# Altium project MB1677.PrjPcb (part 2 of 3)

## Sheet JTAG.SchDoc: JTAG and TRACE
size A4; Date: Not used; ApprovedBy: Not used; CheckedBy: Not used; Author: Not used; CompanyName: STMicroelectronics; DrawnBy: Not used; Engineer: Not used; Organization: Not used; Address1: Not used; Address2: Not used; Address3: Not used; Address4: Not used; DocumentNumber: 14; Revision: Not used; SheetNumber: 14; SheetTotal: 15
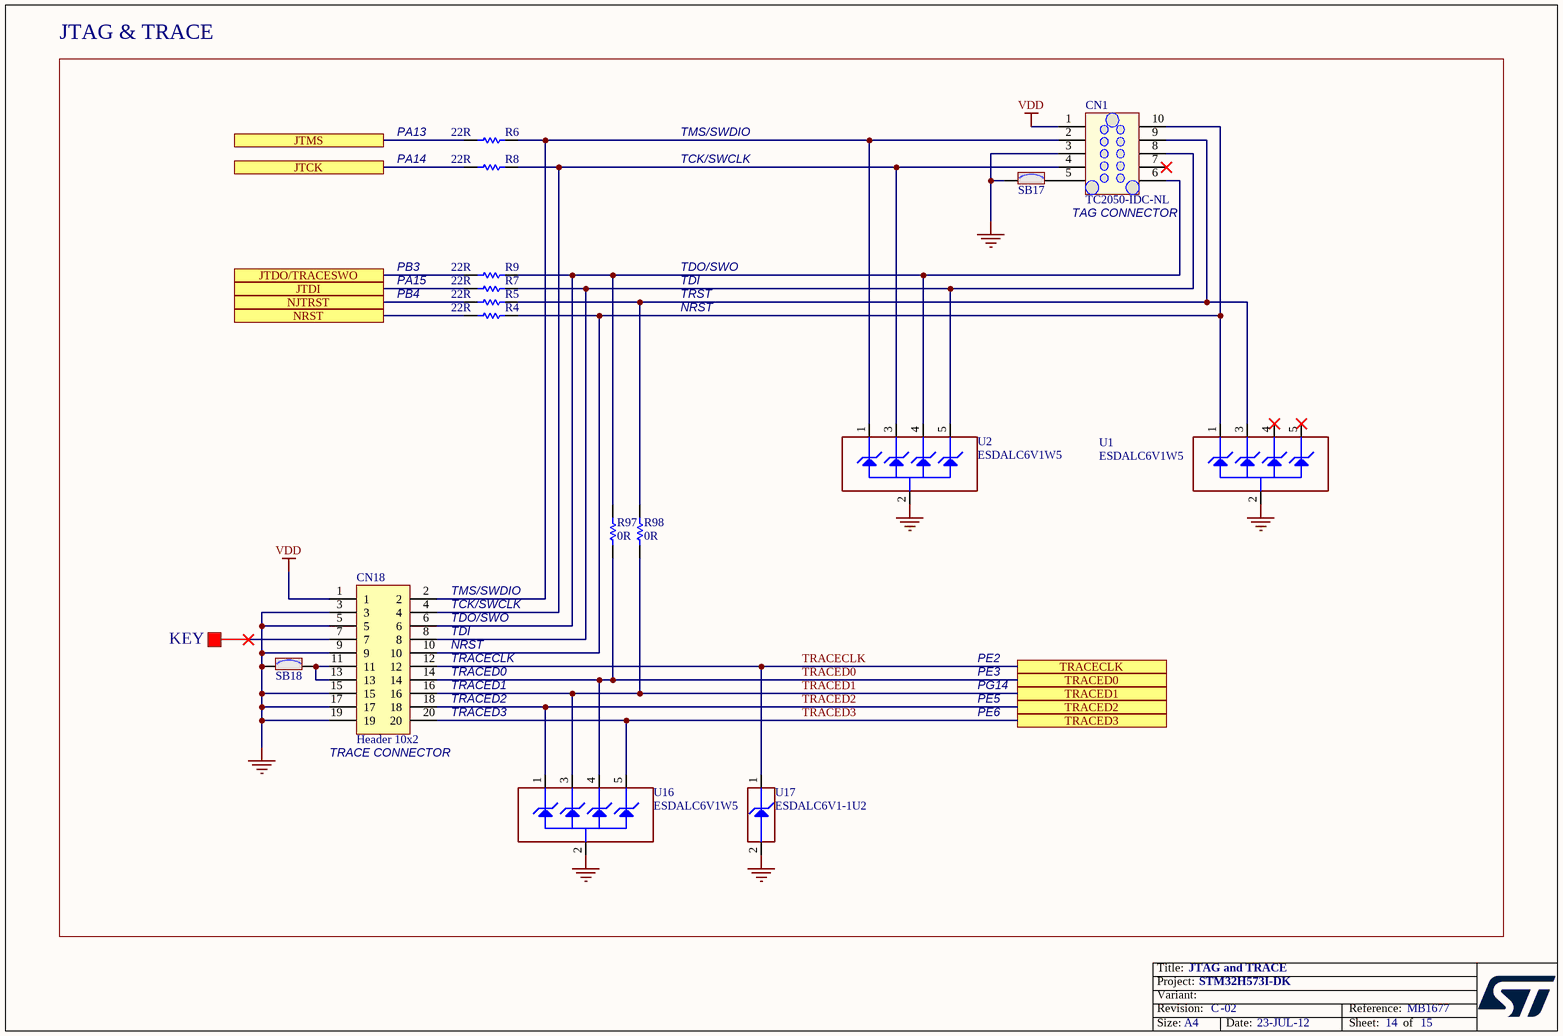
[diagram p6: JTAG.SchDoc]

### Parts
CN1  value TC2050-IDC-NL  [CON_TAG-C_TC2050-IDC-NL]  (hidden comment: Tag-10-C)
CN18  Header 10x2  [CON_SAMTEC_FTSH-110-01-L-DV]
R4  value 22R  [R0603]  (hidden comment: Resistor)
R5  value 22R  [R0603]  (hidden comment: Resistor)
R6  value 22R  [R0603]  (hidden comment: Resistor)
R7  value 22R  [R0603]  (hidden comment: Resistor)
R8  value 22R  [R0603]  (hidden comment: Resistor)
R9  value 22R  [R0603]  (hidden comment: Resistor)
R97  value 0R  [R0402]  (hidden comment: Resistor)
R98  value 0R  [R0402]  (hidden comment: Resistor)
SB17  SB_ON  [SOLDER-BRIDGE_R0603-0R]  (value not drawn)
SB18  SB_ON  [SOLDER-BRIDGE_R0603-0R]  (value not drawn)
U1  ESDALC6V1W5  [ESD_SOT323-5L]
U2  ESDALC6V1W5  [ESD_SOT323-5L]
U16  ESDALC6V1W5  [ESD_SOT323-5L]
U17  value ESDALC6V1-1U2  [ESD_ST0201]  (hidden comment: ESD-TRANSIL)

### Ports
JTCK, JTDI, JTDO/TRACESWO, JTMS, NJTRST, NRST, TRACECLK, TRACED0, TRACED1, TRACED2, TRACED3

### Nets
GND: CN1.3 CN18.3 CN18.5 CN18.9 CN18.15 CN18.17 CN18.19 SB17.1 SB18.1 U1.2(GND) U2.2(GND) U16.2(GND) U17.2(GND)
VDD: CN1.1 CN18.1
JTCK: R8.2 ; port JTCK
JTDI: R7.2 ; port JTDI
JTDO: R9.2 ; port JTDO/TRACESWO
JTMS: R6.2 ; port JTMS
NJTRST: R5.2 ; port NJTRST
NRST: R4.2 ; port NRST
TRACECLK: CN18.12 U17.1(IO1) ; port TRACECLK
TRACED0: CN18.14 R97.1 U16.4(IO3) ; port TRACED0
TRACED1: CN18.16 R98.1 U16.3(IO2) ; port TRACED1
TRACED2: CN18.18 U16.1(IO1) ; port TRACED2
TRACED3: CN18.20 U16.5(IO4) ; port TRACED3
NetCN1_2: CN1.2 CN18.2 R6.1 U2.1(IO1)
NetCN1_4: CN1.4 CN18.4 R8.1 U2.3(IO2)
NetCN1_5: CN1.5 SB17.2
NetCN1_6: CN1.6 CN18.6 R9.1 R97.2 U2.4(IO3)
NetCN1_8: CN1.8 CN18.8 R7.1 U2.5(IO4)
NetCN1_9: CN1.9 R5.1 R98.2 U1.3(IO2)
NetCN1_10: CN1.10 CN18.10 R4.1 U1.1(IO1)
NetCN18_11: CN18.11 CN18.13 SB18.2

Not connected (* = marked no-connect by the designer): CN1 7*; CN18 7*; U1 4(IO3)* 5(IO4)*

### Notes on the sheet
- JTAG & TRACE
- PA13
- PA14
- TMS/SWDIO
- TCK/SWCLK
- TAG CONNECTOR
- PB3
- PA15
- PB4
- TDO/SWO
- TDI
- TRST
- NRST
- KEY
- (near CN18) TMS/SWDIO
- (near CN18) TCK/SWCLK
- (near CN18) TDO/SWO
- (near CN18) TDI
- (near CN18) NRST
- (near CN18) TRACECLK
- (near CN18) TRACED0
- (near CN18) TRACED1
- (near CN18) TRACED2
- (near CN18) TRACED3
- PE2
- PE3
- PG14
- PE5
- PE6
- (near CN18) TRACE CONNECTOR

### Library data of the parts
CN1 = MCD-00031: Tag_Connector Header, 10x2, No legs; Manufacturer_Part_Number: TC2050-IDC-NL-FP; Manufacturer: TAG-CONNECT LLC; Provided_By: SUBCO
CN18 = MCD-00557: Header, 10x2, 1.27mm, VR, SMD, T=3.05mm; BMS_Part_Number: 9183690; Part_Type: Connector; Part_Preference: Recommended; Manufacturer: SAMTEC; Manufacturer_Part_Number: FTSH-110-01-L-DV; Order_Code_RS: 767-6774; Component_Country_Of_Origin: China, Costa Rica, Malaysia, United States, Vietnam; ShowFields: YES; ID: 3188
R4-R9 = MCD-00066: Resistor,22R,0603,1%,1/10W; Manufacturer_Part_Number: RC0603FR-0722RL; Manufacturer: YAGEO; Provided_By: SUBCO
R97 R98 = MCD-00052: Resistor, 0R, 0402, +/-5%, 1/16W; Part_Preference: Recommended; Manufacturer: YAGEO; Manufacturer_Part_Number: RC0402JR-070RL; Order_Code_RS: 618-5804; Component_Country_Of_Origin: China
SB17 SB18 = MCD-00071: Solder Bridge ON; Part_Type: Mechanical; Manufacturer_Part_Number: RC0603JR-070RL; Manufacturer: YAGEO; Provided_By: SUBCO
U1 U2 U16 = MCD-00136: Dual Transil array for ESD protection; Part_Type: Diode; Manufacturer: STMICROELECTRONICS; BMS_Part_Number: 9151112; Provided_By: SUBCO with ST control
U17 = MCD-00170: ESD protection 6V1; BMS_Part_Number: 9151132; Part_Type: Diode; Part_Preference: Recommended; Manufacturer: STMICROELECTRONICS; Manufacturer_HQ_COO: EU; Component_Country_Of_Origin: China; ShowFields: YES; ID: 2696

## Sheet Ethernet.SchDoc: Ethernet
size A4; Date: Not used; ApprovedBy: Not used; CheckedBy: Not used; Author: Not used; CompanyName: STMicroelectronics; DrawnBy: Not used; Engineer: Not used; Organization: Not used; Address1: Not used; Address2: Not used; Address3: Not used; Address4: Not used; DocumentNumber: 9; Revision: Not used; SheetNumber: 9; SheetTotal: 15
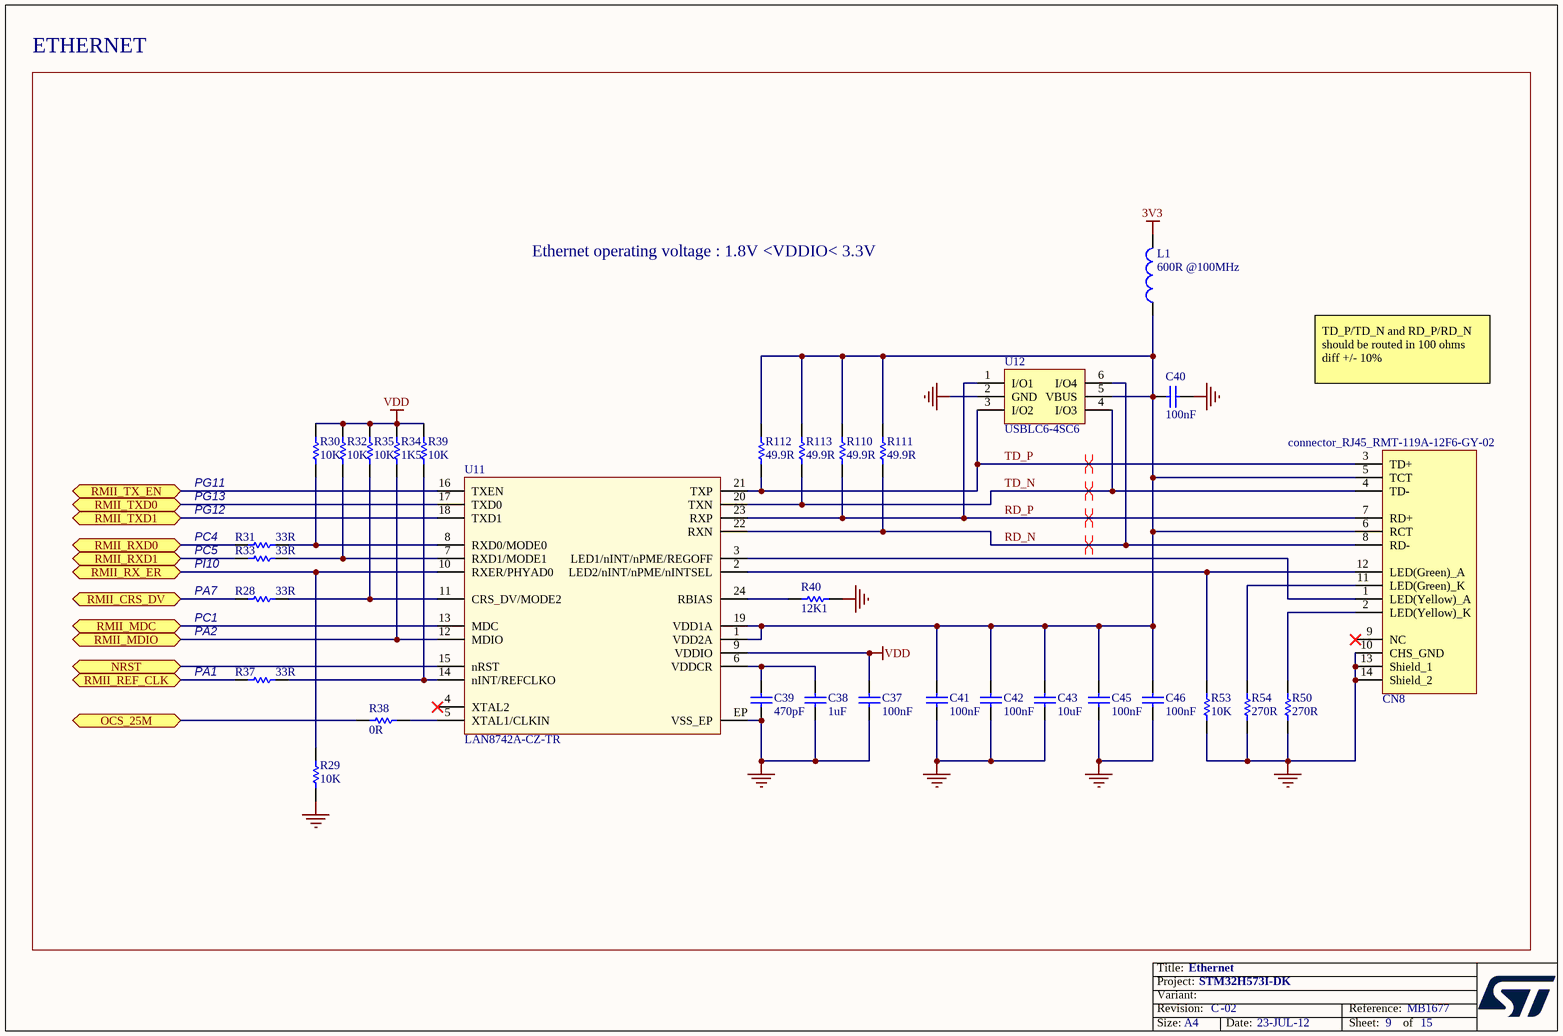
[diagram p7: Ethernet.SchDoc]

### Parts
C37  value 100nF  [C0603]  (hidden comment: Capacitor)
C38  value 1uF  [C0402]  (hidden comment: Capacitor)
C39  value 470pF  [C0402]  (hidden comment: Capacitor)
C40  value 100nF  [C0603]  (hidden comment: Capacitor)
C41  value 100nF  [C0603]  (hidden comment: Capacitor)
C42  value 100nF  [C0603]  (hidden comment: Capacitor)
C43  value 10uF  [C0603]  (hidden comment: Capacitor)
C45  value 100nF  [C0603]  (hidden comment: Capacitor)
C46  value 100nF  [C0603]  (hidden comment: Capacitor)
CN8  value connector_RJ45_RMT-119A-12F6-GY-02  [CON_RJ45_PHC_RMT-119A-12F6-GY-02]  (hidden comment: RJ45_RTS-119A-12F6-GY-02)
L1  value 600R @100MHz  [L0603]  (hidden comment: BEAD)
R28  value 33R  [R0402]  (hidden comment: Resistor)
R29  value 10K  [R0402]  (hidden comment: Resistor)
R30  value 10K  [R0402]  (hidden comment: Resistor)
R31  value 33R  [R0402]  (hidden comment: Resistor)
R32  value 10K  [R0402]  (hidden comment: Resistor)
R33  value 33R  [R0402]  (hidden comment: Resistor)
R34  value 1K5  [R0402]  (hidden comment: Resistor)
R35  value 10K  [R0402]  (hidden comment: Resistor)
R37  value 33R  [R0402]  (hidden comment: Resistor)
R38  value 0R  [R0402]  (hidden comment: Resistor)
R39  value 10K  [R0402]  (hidden comment: Resistor)
R40  value 12K1  [R0402]  (hidden comment: Resistor)
R50  value 270R  [R0402]  (hidden comment: Resistor)
R53  value 10K  [R0402]  (hidden comment: Resistor)
R54  value 270R  [R0402]  (hidden comment: Resistor)
R110  value 49.9R  [R0402]  (hidden comment: Resistor)
R111  value 49.9R  [R0402]  (hidden comment: Resistor)
R112  value 49.9R  [R0402]  (hidden comment: Resistor)
R113  value 49.9R  [R0402]  (hidden comment: Resistor)
U11  LAN8742A-CZ-TR  [ICC_VQFN24-EPAD_4X4_P050]
U12  USBLC6-4SC6  [ESD_SOT23-6L]

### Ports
NRST (bidir), OCS_25M (bidir), RMII_CRS_DV (bidir), RMII_MDC (bidir), RMII_MDIO (bidir), RMII_REF_CLK (bidir), RMII_RX_ER (bidir), RMII_RXD0 (bidir), RMII_RXD1 (bidir), RMII_TX_EN (bidir), RMII_TXD0 (bidir), RMII_TXD1 (bidir)

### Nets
3V3: L1.2
GND: C37.1 C38.1 C39.1 C40.2 C41.1 C42.1 C43.1 C45.1 C46.1 CN8.10(CHS_GND) CN8.13(Shield_1) CN8.14(Shield_2) R29.2 R40.2 R50.1 R53.1 R54.1 U11.EP(VSS_EP) U12.2(GND)
VDD: C37.2 R30.2 R32.2 R34.2 R35.2 R39.2 U11.9(VDDIO)
NRST: U11.15(nRST) ; port NRST
OCS_25M: R38.2 ; port OCS_25M
RD_N: CN8.8(RD-) R111.1 U11.22(RXN) U12.6(I/O4)
RD_P: CN8.7(RD+) R110.1 U11.23(RXP) U12.1(I/O1)
RMII_CRS_DV: R28.1 ; port RMII_CRS_DV
RMII_MDC: U11.13(MDC) ; port RMII_MDC
RMII_MDIO: R34.1 U11.12(MDIO) ; port RMII_MDIO
RMII_REF_CLK: R37.1 ; port RMII_REF_CLK
RMII_RX_ER: R29.1 U11.10(RXER/PHYAD0) ; port RMII_RX_ER
RMII_RXD0: R31.1 ; port RMII_RXD0
RMII_RXD1: R33.1 ; port RMII_RXD1
RMII_TX_EN: U11.16(TXEN) ; port RMII_TX_EN
RMII_TXD0: U11.17(TXD0) ; port RMII_TXD0
RMII_TXD1: U11.18(TXD1) ; port RMII_TXD1
TD_N: CN8.4(TD-) R113.1 U11.20(TXN) U12.4(I/O3)
TD_P: CN8.3(TD+) R112.1 U11.21(TXP) U12.3(I/O2)
NetC38_2: C38.2 C39.2 U11.6(VDDCR)
NetC40_1: C40.1 C41.2 C42.2 C43.2 C45.2 C46.2 CN8.5(TCT) CN8.6(RCT) L1.1 R110.2 R111.2 R112.2 R113.2 U11.1(VDD2A) U11.19(VDD1A) U12.5(VBUS)
NetCN8_1: CN8.1(LED(Yellow)_A) U11.3(LED1/nINT/nPME/REGOFF)
NetCN8_2: CN8.2(LED(Yellow)_K) R50.2
NetCN8_11: CN8.11(LED(Green)_K) R54.2
NetCN8_12: CN8.12(LED(Green)_A) R53.2 U11.2(LED2/nINT/nPME/nINTSEL)
NetR28_2: R28.2 R35.1 U11.11(CRS_DV/MODE2)
NetR30_1: R30.1 R31.2 U11.8(RXD0/MODE0)
NetR32_1: R32.1 R33.2 U11.7(RXD1/MODE1)
NetR37_2: R37.2 R39.1 U11.14(nINT/REFCLKO)
NetR38_1: R38.1 U11.5(XTAL1/CLKIN)
NetR40_1: R40.1 U11.24(RBIAS)

Not connected (* = marked no-connect by the designer): CN8 9(NC)*; U11 4(XTAL2)*

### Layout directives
differential pair: RD_N, RD_P, TD_N, TD_P

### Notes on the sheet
- ETHERNET
- Ethernet operating voltage : 1.8V <VDDIO< 3.3V
- TD_P/TD_N and RD_P/RD_N should be routed in 100 ohms diff +/- 10%
- PG11
- PG13
- PG12
- PC4
- PC5
- PI10
- PA7
- (near R28) PC1
- PA2
- (near R37) PA1

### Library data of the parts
C37 C40-C42 C45 C46 = MCD-00237: Capacitor, MLCC, 100nF, 6V3, X5R, 10%, 0603, T=0,8mm; Manufacturer_Part_Number: CC0603KRX5R5BB104; Manufacturer: YAGEO; Provided_By: SUBCO; ECCN_US: EAR99; ECCN_EU: NEC
C38 = MCD-00095: Capacitor, MLCC, 1uF, 6V3, X5R, 10%, 0402, T=0,5mm; Manufacturer_Part_Number: GRM155R61E105KA12; Manufacturer: MURATA; Alternate_Manufacturer_Part_Number: GRM155R60J105KE19; Provided_By: SUBCO; ECCN_US: EAR99; ECCN_EU: NEC
C39 = MCD-00724: Capacitor, MLCC, 470pF, 50V, NPO, 5%, 0402, T=0,5mm; Manufacturer_Part_Number: CC0402JRNPO9BN471; Manufacturer: YAGEO; Provided_By: SUBCO
C43 = MCD-01124: Capacitor, MLCC, 10µF, 10V, X5R, 10%, 0603, T=0.8mm; Manufacturer_Part_Number: GRM188R61A106KAAL; Manufacturer: MURATA; Provided_By: SUBCO; ECCN_US: EAR99; ECCN_EU: NEC
CN8 = MCD-02475: connector_RJ45, 10/100 Ethernet integrated MAG with integrate Green and Yellow LED, T= 13.61mm; Part_Preference: Recommended; Manufacturer: PENGHUI; Manufacturer_Part_Number: RMT-119A-12F6-GY-02
L1 = MCD-02437: Ferrite bead, 600R@100MHz, +/-25%, 500mA, 380mR, 0603, T=0.8mm; Part_Type: Inductor; Part_Preference: Recommended; Manufacturer: MURATA; Manufacturer_Part_Number: BLM18AG601SN1D; Order_Code_RS: 724-1299
R28 R31 R33 R37 = MCD-00455: Resistor,33R,0402,1%,1/16W; Manufacturer_Part_Number: RC0402FR-0733RL; Manufacturer: YAGEO; Provided_By: SUBCO; ECCN_US: EAR99; ECCN_EU: NEC
R29 R30 R32 R35 R39 R53 = MCD-00053: Resistor,10K,0402,1%,1/16W; Manufacturer_Part_Number: RC0402FR-0710KL; Manufacturer: YAGEO; Provided_By: SUBCO; ECCN_US: EAR99; ECCN_EU: NEC
R34 = MCD-00068: Resistor,1K5,0402,1%,1/16W; Manufacturer_Part_Number: RC0402FR-071K5L; Manufacturer: YAGEO; Provided_By: SUBCO; ECCN_US: EAR99; ECCN_EU: NEC
R38 = MCD-00052: Resistor,0R,0402,5%,1/16W; Manufacturer_Part_Number: RC0402JR-070RL; Manufacturer: YAGEO; Provided_By: SUBCO; ECCN_US: EAR99; ECCN_EU: NEC
R40 = MCD-00723: Resistor,12K1,0402,1%,1/16W; Manufacturer_Part_Number: RC0402FR-0712K1L; Manufacturer: YAGEO; Provided_By: SUBCO; ECCN_US: EAR99; ECCN_EU: NEC
R50 R54 = MCD-00441: Resistor,270R,0402,1%,1/16W; Manufacturer_Part_Number: RC0402FR-07270RL; Manufacturer: YAGEO; Provided_By: SUBCO; ECCN_US: EAR99; ECCN_EU: NEC
R110-R113 = MCD-00565: Resistor,49R9,0402,1%,1/16W; Manufacturer_Part_Number: RC0402FR-0749R9L; Manufacturer: YAGEO; Provided_By: SUBCO; ECCN_US: EAR99; ECCN_EU: NEC
U11 = MCD-00719: 10/100M RMII Ethernet transceiver; Part_Type: IC; Manufacturer: MICROCHIP; Provided_By: SUBCO
U12 = MCD-00250: Very low capacitance ESD protection , 4 lines; Part_Type: IC; Manufacturer: STMICROELECTRONICS; BMS_Part_Number: 9151001; Provided_By: SUBCO with ST control; ECCN_US: EAR99; ECCN_EU: NEC

## Sheet STLINK_V3EC.SchDoc: STLINK-V3EC
size A3; Date: Not used; ApprovedBy: Not used; CheckedBy: Not used; Author: Not used; CompanyName: STMicroelectronics; DrawnBy: Not used; Engineer: Not used; Organization: Not used; Address1: Not used; Address2: Not used; Address3: Not used; Address4: Not used; DocumentNumber: 15; Revision: Not used; SheetNumber: 15; SheetTotal: 15
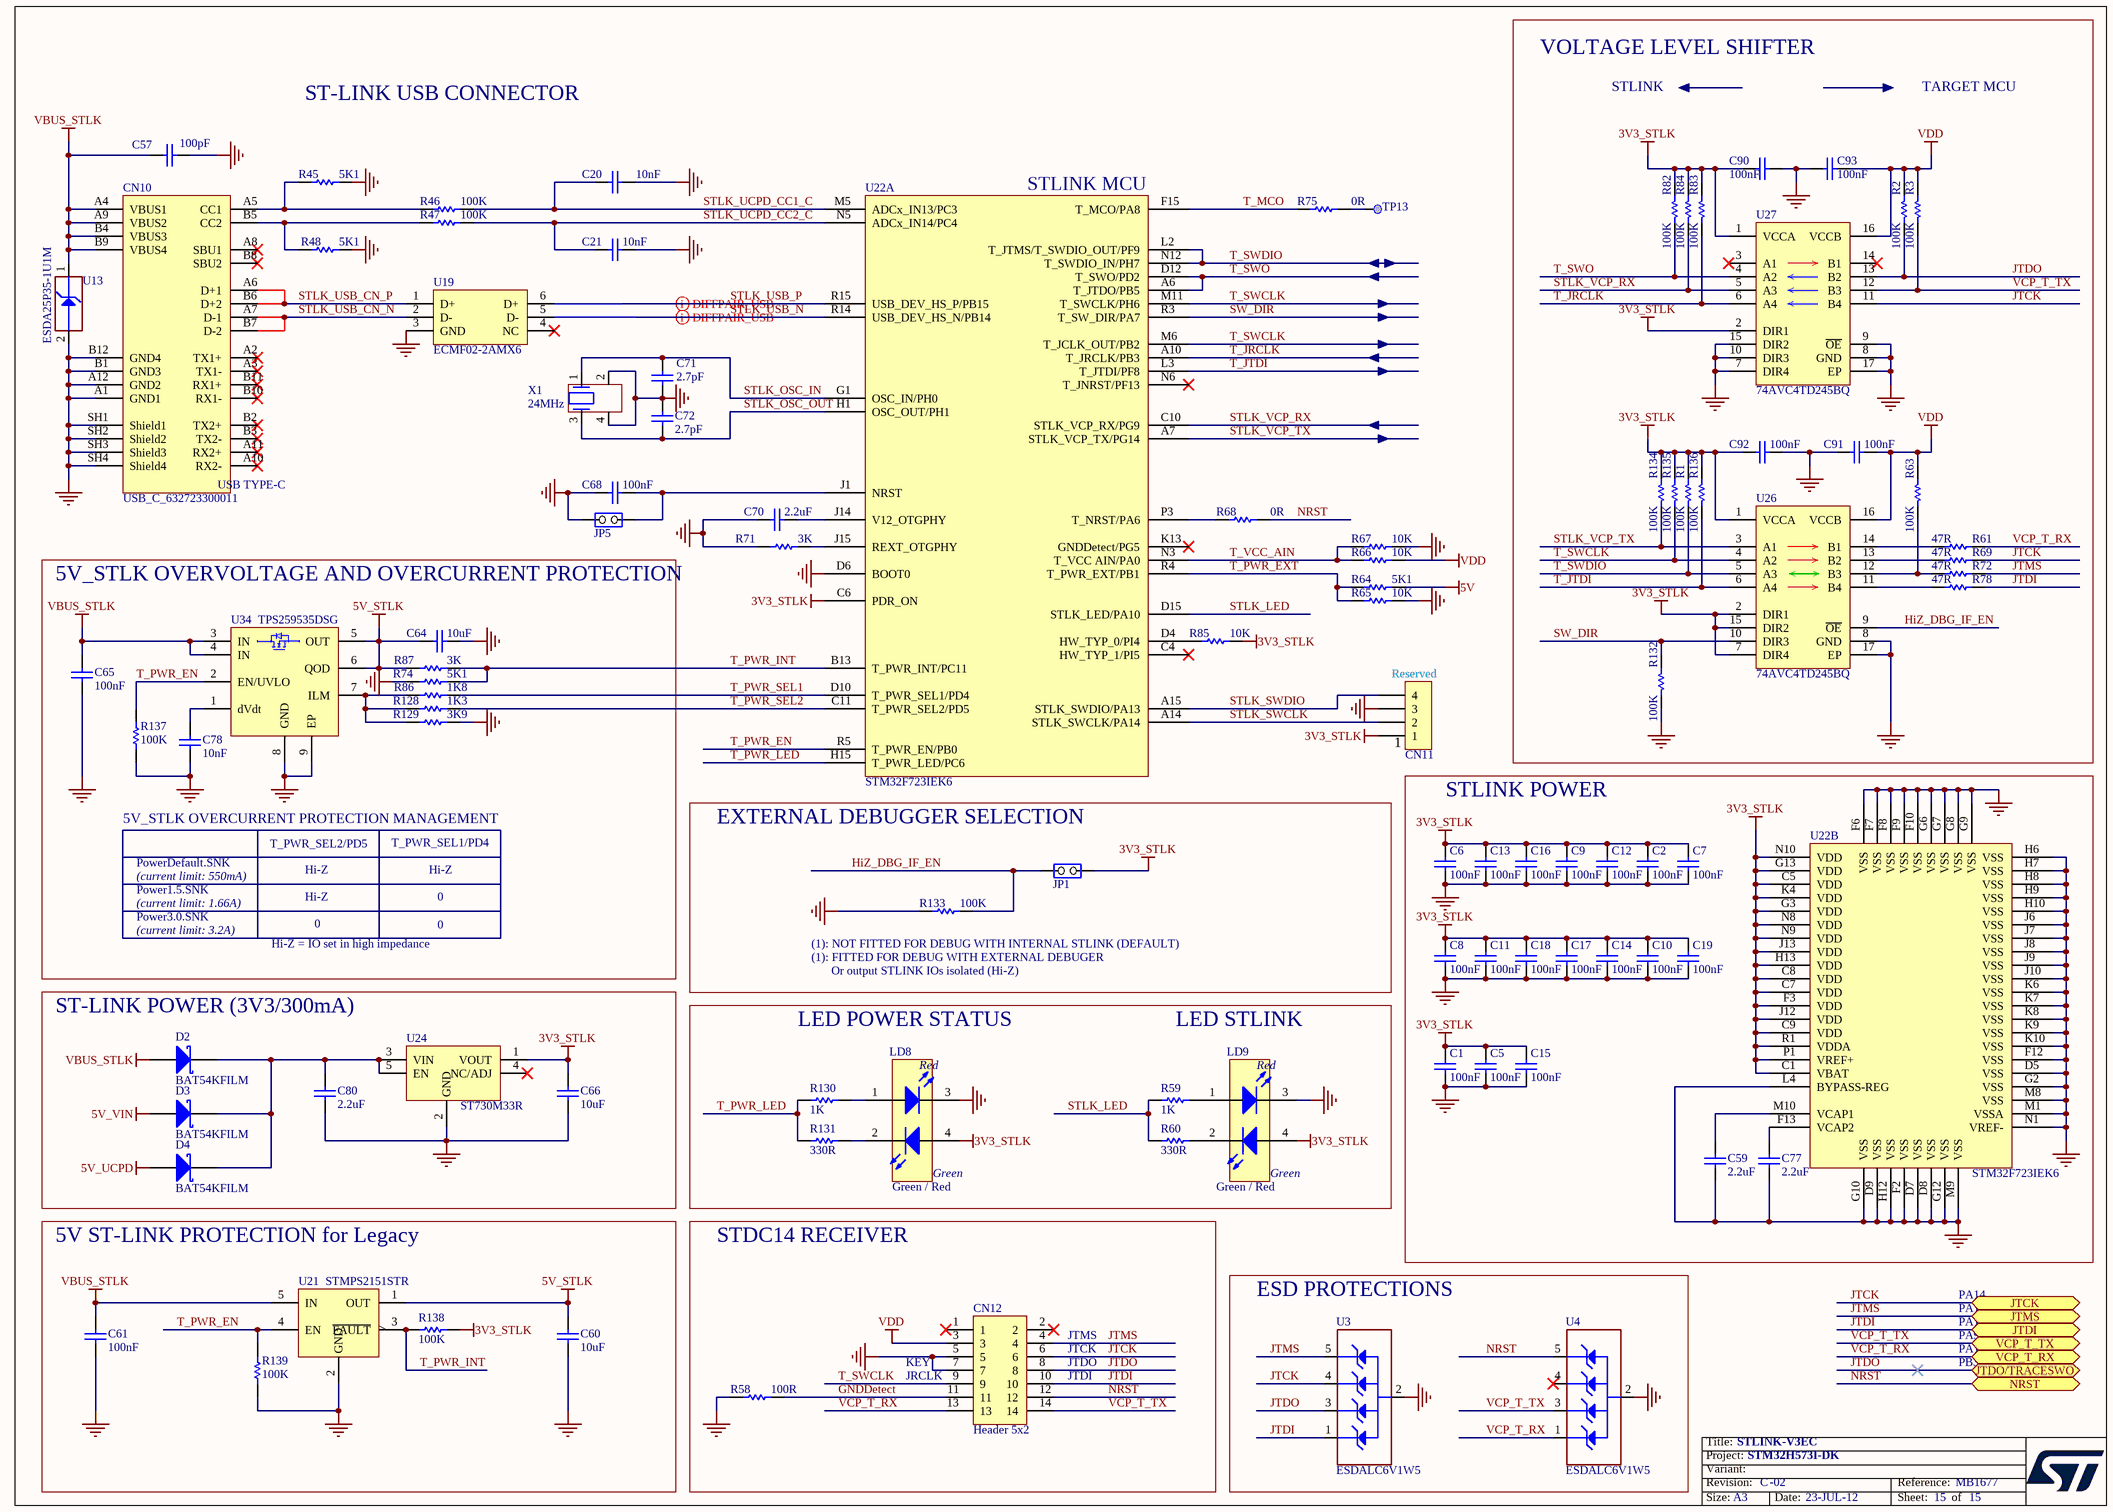
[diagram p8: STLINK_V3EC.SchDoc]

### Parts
C1  value 100nF  [C0402]  (hidden comment: Capacitor)
C2  value 100nF  [C0402]  (hidden comment: Capacitor)
C5  value 100nF  [C0402]  (hidden comment: Capacitor)
C6  value 100nF  [C0402]  (hidden comment: Capacitor)
C7  value 100nF  [C0402]  (hidden comment: Capacitor)
C8  value 100nF  [C0402]  (hidden comment: Capacitor)
C9  value 100nF  [C0402]  (hidden comment: Capacitor)
C10  value 100nF  [C0402]  (hidden comment: Capacitor)
C11  value 100nF  [C0402]  (hidden comment: Capacitor)
C12  value 100nF  [C0402]  (hidden comment: Capacitor)
C13  value 100nF  [C0402]  (hidden comment: Capacitor)
C14  value 100nF  [C0402]  (hidden comment: Capacitor)
C15  value 100nF  [C0402]  (hidden comment: Capacitor)
C16  value 100nF  [C0402]  (hidden comment: Capacitor)
C17  value 100nF  [C0402]  (hidden comment: Capacitor)
C18  value 100nF  [C0402]  (hidden comment: Capacitor)
C19  value 100nF  [C0402]  (hidden comment: Capacitor)
C20  value 10nF  [C0402]  (hidden comment: Capacitor)
C21  value 10nF  [C0402]  (hidden comment: Capacitor)
C57  value 100pF  [C0402]  (hidden comment: Capacitor)
C59  value 2.2uF  [C0402]  (hidden comment: Capacitor)
C60  value 10uF  [C0603]  (hidden comment: Capacitor)
C61  value 100nF  [C0402]  (hidden comment: Capacitor)
C64  value 10uF  [C0603]  (hidden comment: Capacitor)
C65  value 100nF  [C0402]  (hidden comment: Capacitor)
C66  value 10uF  [C0603]  (hidden comment: Capacitor)
C68  value 100nF  [C0402]  (hidden comment: Capacitor)
C70  value 2.2uF  [C0402]  (hidden comment: Capacitor)
C71  value 2.7pF  [C0402]  (hidden comment: Capacitor)
C72  value 2.7pF  [C0402]  (hidden comment: Capacitor)
C77  value 2.2uF  [C0402]  (hidden comment: Capacitor)
C78  value 10nF  [C0402]  (hidden comment: Capacitor)
C80  value 2.2uF  [C0805]  (hidden comment: Capacitor)
C90  value 100nF  [C0402]  (hidden comment: Capacitor)
C91  value 100nF  [C0402]  (hidden comment: Capacitor)
C92  value 100nF  [C0402]  (hidden comment: Capacitor)
C93  value 100nF  [C0402]  (hidden comment: Capacitor)
CN10  value USB_C_632723300011  [CON_USB-TYPEC_WE_632723300011]  (hidden comment: USB_TYPE_C_Receptacle)
CN11  Header 4x1  [CON_SAMTEC_TSW-104-07-G-S]  (value not drawn)
CN12  value Header 5x2  [CON_STDC14_Receiver_MEDIUM_WITH_MIPI10_3D]  (hidden comment: Header 7x2)
D2  value BAT54KFILM  [DIO_SOD523_1A_2K]  (hidden comment: SCHOTTKY_1A_2K)
D3  value BAT54KFILM  [DIO_SOD523_1A_2K]  (hidden comment: SCHOTTKY_1A_2K)
D4  value BAT54KFILM  [DIO_SOD523_1A_2K]  (hidden comment: SCHOTTKY_1A_2K)
JP1  Jumper_Header 2x1  [CON_SAMTEC_TSW-102-07-G-S]  (value not drawn)
JP5  Jumper_Header 2x1  [CON_SAMTEC_TSW-102-07-G-S]  (value not drawn)
LD8  value Green / Red  [LED_BI-GR_WE-150141SV73110]  (hidden comment: LED_BICOLOR)
LD9  value Green / Red  [LED_BI-GR_WE-150141SV73110]  (hidden comment: LED_BICOLOR)
R1  value 100K  [R0402]  (hidden comment: Resistor)
R2  value 100K  [R0402]  (hidden comment: Resistor)
R3  value 100K  [R0402]  (hidden comment: Resistor)
R45  value 5K1  [R0402]  (hidden comment: Resistor)
R46  value 100K  [R0402]  (hidden comment: Resistor)
R47  value 100K  [R0402]  (hidden comment: Resistor)
R48  value 5K1  [R0402]  (hidden comment: Resistor)
R58  value 100R  [R0402]  (hidden comment: Resistor)
R59  value 1K  [R0402]  (hidden comment: Resistor)
R60  value 330R  [R0402]  (hidden comment: Resistor)
R61  value 47R  [R0402]  (hidden comment: Resistor)
R63  value 100K  [R0402]  (hidden comment: Resistor)
R64  value 5K1  [R0402]  (hidden comment: Resistor)
R65  value 10K  [R0402]  (hidden comment: Resistor)
R66  value 10K  [R0402]  (hidden comment: Resistor)
R67  value 10K  [R0402]  (hidden comment: Resistor)
R68  value 0R  [R0402]  (hidden comment: Resistor)
R69  value 47R  [R0402]  (hidden comment: Resistor)
R71  value 3K  [R0402]  (hidden comment: Resistor)
R72  value 47R  [R0402]  (hidden comment: Resistor)
R74  value 5K1  [R0402]  (hidden comment: Resistor)
R75  value 0R  [R0402]  (hidden comment: Resistor)
R78  value 47R  [R0402]  (hidden comment: Resistor)
R82  value 100K  [R0402]  (hidden comment: Resistor)
R83  value 100K  [R0402]  (hidden comment: Resistor)
R84  value 100K  [R0402]  (hidden comment: Resistor)
R85  value 10K  [R0402]  (hidden comment: Resistor)
R86  value 1K8  [R0402]  (hidden comment: Resistor)
R87  value 3K  [R0402]  (hidden comment: Resistor)
R128  value 1K3  [R0402]  (hidden comment: Resistor)
R129  value 3K9  [R0402]  (hidden comment: Resistor)
R130  value 1K  [R0402]  (hidden comment: Resistor)
R131  value 330R  [R0402]  (hidden comment: Resistor)
R132  value 100K  [R0402]  (hidden comment: Resistor)
R133  value 100K  [R0402]  (hidden comment: Resistor)
R134  value 100K  [R0402]  (hidden comment: Resistor)
R135  value 100K  [R0402]  (hidden comment: Resistor)
R136  value 100K  [R0402]  (hidden comment: Resistor)
R137  value 100K  [R0402]  (hidden comment: Resistor)
R138  value 100K  [R0402]  (hidden comment: Resistor)
R139  value 100K  [R0402]  (hidden comment: Resistor)
TP13  Test Point  [TP_SMD_1MM]  (value not drawn)  (no BOM)
U3  ESDALC6V1W5  [ESD_SOT323-5L]
U4  ESDALC6V1W5  [ESD_SOT323-5L]
U13  value ESDA25P35-1U1M  [ESD_QFN1610_2N_1K_2A]  (hidden comment: ESD-TRANSIL)
U19  ECMF02-2AMX6  [ESD_QFN-6L_1P7X1P5_P050]
U21  STMPS2151STR  [MOS_SOT23-5L]
U22  value STM32F723IEK6  [ICC_UFBGA201_176+25_10X10_P065]  (hidden comment: STLINK-V3EC)  (parts A,B of 2)
U24  ST730M33R  [ICC_SOT23-5L_H1P45]
U26  74AVC4TD245BQ  [ICC_DHVQFN16-EPAD_SOT763-1_2P5X3P5_H0P85_P050]
U27  74AVC4TD245BQ  [ICC_DHVQFN16-EPAD_SOT763-1_2P5X3P5_H0P85_P050]
U34  TPS259535DSG  [ICC_WSON8-EPAD_2X2_P050]
X1  value 24MHz  [CRY_NX2016SA_4P]  (hidden comment: XTAL_4_PINS)

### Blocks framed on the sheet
VOLTAGE LEVEL SHIFTER: C90-C93 R1-R3 R61 R63 R69 R72 R78 R82-R84 R132 R134-R136 U26 U27
5V_STLK OVERVOLTAGE AND OVERCURRENT PROTECTION: C64 C65 C78 R74 R86 R87 R128 R129 R137 U34
STLINK POWER: C1 C2 C5-C19 C59 C77 U22
EXTERNAL DEBUGGER SELECTION: JP1 R133
ST-LINK POWER (3V3/300mA): C66 C80 D2-D4 U24
5V ST-LINK PROTECTION for Legacy: C60 C61 R138 R139 U21
STDC14 RECEIVER: CN12 R58
ESD PROTECTIONS: U3 U4

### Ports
JTCK (bidir), JTDI (bidir), JTDO/TRACESWO (bidir), JTMS (bidir), NRST (bidir), VCP_T_RX (bidir), VCP_T_TX (bidir)

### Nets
3V3_STLK: C1.1 C2.1 C5.1 C6.1 C7.1 C8.1 C9.1 C10.1 C11.1 C12.1 C13.1 C14.1 C15.1 C16.1 C17.1 C18.1 C19.1 C66.2 C90.2 C92.2 CN11.1 JP1.1(COMMON) LD8.4(Green_anode) LD9.4(Green_anode) R1.2 R82.2 R83.2 R84.2 R85.2 R134.1 R135.2 R136.2 R138.1 U22.C1(VBAT) U22.C5(VDD) U22.C6(PDR_ON) U22.C7(VDD) U22.C8(VDD) U22.C9(VDD) U22.F3(VDD) U22.G3(VDD) U22.G13(VDD) U22.H13(VDD) U22.J12(VDD) U22.J13(VDD) U22.K4(VDD) U22.N8(VDD) U22.N9(VDD) U22.N10(VDD) U22.P1(VREF+) U22.R1(VDDA) U24.1(VOUT) U26.1(VCCA) U26.2(DIR1) U26.7(DIR4) U26.15(DIR2) U27.1(VCCA) U27.2(DIR1)
5V: R64.2
5V_STLK: C60.2 C64.2 R87.1 U21.1(OUT) U34.5(OUT) U34.6(QOD)
5V_UCPD: D4.1(A)
5V_VIN: D3.1(A)
GND: C1.2 C2.2 C5.2 C6.2 C7.2 C8.2 C9.2 C10.2 C11.2 C12.2 C13.2 C14.2 C15.2 C16.2 C17.2 C18.2 C19.2 C20.2 C21.2 C57.2 C59.1 C60.1 C61.1 C64.1 C65.1 C66.1 C68.1 C70.1 C71.1 C72.2 C77.1 C78.1 C80.1 C90.1 C91.2 C92.1 C93.2 CN10.A1(GND1) CN10.A12(GND2) CN10.B1(GND3) CN10.B12(GND4) CN10.SH1(Shield1) CN10.SH2(Shield2) CN10.SH3(Shield3) CN10.SH4(Shield4) CN11.3 CN12.5 CN12.7 JP5.2(NO) LD8.3(RED_cathode) LD9.3(RED_cathode) R45.2 R48.2 R58.1 R65.2 R67.2 R71.2 R74.1 R129.2 R132.1 R133.1 R137.1 R139.1 U3.2(GND) U4.2(GND) U13.2(GND) U19.3(GND) U21.2(GND) U22.D5(VSS) U22.D6(BOOT0) U22.D7(VSS) U22.D8(VSS) U22.D9(VSS) U22.F2(VSS) U22.F6(VSS) U22.F7(VSS) U22.F8(VSS) U22.F9(VSS) U22.F10(VSS) U22.F12(VSS) U22.G2(VSS) U22.G6(VSS) U22.G7(VSS) U22.G8(VSS) U22.G9(VSS) U22.G10(VSS) U22.G12(VSS) U22.H6(VSS) U22.H7(VSS) U22.H8(VSS) U22.H9(VSS) U22.H10(VSS) U22.H12(VSS) U22.J6(VSS) U22.J7(VSS) U22.J8(VSS) U22.J9(VSS) U22.J10(VSS) U22.K6(VSS) U22.K7(VSS) U22.K8(VSS) U22.K9(VSS) U22.K10(VSS) U22.L4(BYPASS-REG) U22.M1(VSSA) U22.M8(VSS) U22.M9(VSS) U22.N1(VREF-) U24.2(GND) U26.8(GND) U26.17(EP) U27.7(DIR4) U27.8(GND) U27.9(~{OE}) U27.10(DIR3) U27.15(DIR2) U27.17(EP) U34.8(GND) U34.9(EP) X1.2 X1.4
VBUS_STLK: C57.1 C61.2 C65.2 CN10.A4(VBUS1) CN10.A9(VBUS2) CN10.B4(VBUS3) CN10.B9(VBUS4) D2.1(A) U13.1(IO1) U21.5(IN) U34.3(IN) U34.4(IN)
VDD: C91.1 C93.1 CN12.3 R2.2 R3.2 R63.2 R66.2 U26.16(VCCB) U27.16(VCCB)
GNDDetect: CN12.11 R58.2
HiZ_DBG_IF_EN: JP1.2(NO) R133.2 U26.9(~{OE})
JTCK: CN12.6 R69.2 U3.4(IO3) U27.11(B4) ; port JTCK
JTDI: CN12.10 R78.2 U3.1(IO1) ; port JTDI
JTDO: CN12.8 R2.1 U3.3(IO2) U27.13(B2) ; port JTDO/TRACESWO
JTMS: CN12.4 R72.2 U3.5(IO4) ; port JTMS
NRST: CN12.12 R68.2 U4.5(IO4) ; port NRST
STLK_LED: R59.2 R60.1 U22.D15(STLK_LED/PA10)
STLK_OSC_IN: C71.2 U22.G1(OSC_IN/PH0) X1.1
STLK_OSC_OUT: C72.1 U22.H1(OSC_OUT/PH1) X1.3
STLK_SWCLK: CN11.2 U22.A14(STLK_SWCLK/PA14)
STLK_SWDIO: CN11.4 U22.A15(STLK_SWDIO/PA13)
STLK_UCPD_CC1_C: C20.1 R46.2 U22.M5(ADCx_IN13/PC3)
STLK_UCPD_CC2_C: C21.1 R47.2 U22.N5(ADCx_IN14/PC4)
STLK_USB_CN_N: CN10.A7(D-1) CN10.B7(D-2) U19.2(D-)
STLK_USB_CN_P: CN10.A6(D+1) CN10.B6(D+2) U19.1(D+)
STLK_USB_N: U19.5(D-) U22.R14(USB_DEV_HS_N/PB14)
STLK_USB_P: U19.6(D+) U22.R15(USB_DEV_HS_P/PB15)
STLK_VCP_RX: R84.1 U22.C10(STLK_VCP_RX/PG9) U27.5(A3)
STLK_VCP_TX: R134.2 U22.A7(STLK_VCP_TX/PG14) U26.3(A1)
SW_DIR: R132.2 U22.R3(T_SW_DIR/PA7) U26.10(DIR3)
T_JRCLK: R83.1 U22.A10(T_JRCLK/PB3) U27.6(A4)
T_JTDI: R136.1 U22.L3(T_JTDI/PF8) U26.6(A4)
T_MCO: R75.1 U22.F15(T_MCO/PA8)
T_PWR_EN: R137.2 R139.2 U21.4(EN) U22.R5(T_PWR_EN/PB0) U34.2(EN/UVLO)
T_PWR_EXT: R64.1 R65.1 U22.R4(T_PWR_EXT/PB1)
T_PWR_INT: R74.2 R87.2 R138.2 U21.3(~{FAULT}) U22.B13(T_PWR_INT/PC11)
T_PWR_LED: R130.2 R131.2 U22.H15(T_PWR_LED/PC6)
T_PWR_SEL1: R86.2 U22.D10(T_PWR_SEL1/PD4)
T_PWR_SEL2: R128.2 U22.C11(T_PWR_SEL2/PD5)
T_SWCLK: CN12.9 R135.1 U22.M6(T_JCLK_OUT/PB2) U22.M11(T_SWCLK/PH6) U26.4(A2)
T_SWDIO: R1.1 U22.L2(T_JTMS/T_SWDIO_OUT/PF9) U22.N12(T_SWDIO_IN/PH7) U26.5(A3)
T_SWO: R82.1 U22.A6(T_JTDO/PB5) U22.D12(T_SWO/PD2) U27.4(A2)
T_VCC_AIN: R66.1 R67.1 U22.N3(T_VCC_AIN/PA0)
VCP_T_RX: CN12.13 R61.2 U4.1(IO1) ; port VCP_T_RX
VCP_T_TX: CN12.14 R3.1 U4.3(IO2) U27.12(B3) ; port VCP_T_TX
NetC59_2: C59.2 U22.M10(VCAP1)
NetC68_2: C68.2 JP5.1(COMMON) U22.J1(NRST)
NetC70_2: C70.2 U22.J14(V12_OTGPHY)
NetC77_2: C77.2 U22.F13(VCAP2)
NetC78_2: C78.2 U34.1(dVdt)
NetC80_2: C80.2 D2.2(K) D3.2(K) D4.2(K) U24.3(VIN) U24.5(EN)
NetCN10_A5: CN10.A5(CC1) R45.1 R46.1
NetCN10_B5: CN10.B5(CC2) R47.1 R48.1
NetLD8_1: LD8.1(Red_anode) R130.1
NetLD8_2: LD8.2(Green_cathode) R131.1
NetLD9_1: LD9.1(Red_anode) R59.1
NetLD9_2: LD9.2(Green_cathode) R60.2
NetR61_1: R61.1 U26.14(B1)
NetR63_1: R63.1 R72.1 U26.12(B3)
NetR68_1: R68.1 U22.P3(T_NRST/PA6)
NetR69_1: R69.1 U26.13(B2)
NetR71_1: R71.1 U22.J15(REXT_OTGPHY)
NetR75_2: R75.2 TP13.1
NetR78_1: R78.1 U26.11(B4)
NetR85_1: R85.1 U22.D4(HW_TYP_0/PI4)
NetR86_1: R86.1 R128.1 R129.1 U34.7(ILM)

Not connected (* = marked no-connect by the designer): CN10 A2(TX1+)* A3(TX1-)* A8(SBU1)* A10(RX2-)* A11(RX2+)* B2(TX2+)* B3(TX2-)* B8(SBU2)* B10(RX1-)* B11(RX1+)*; CN12 1* 2*; U4 4(IO3)*; U19 4(NC)*; U22 C4(HW_TYP_1/PI5)* K13(GNDDetect/PG5)* N6(T_JNRST/PF13)*; U24 4(NC/ADJ)*; U27 3(A1)* 14(B1)*

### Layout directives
differential pair; rule Impedance Constraint [Min = 85.00    Max = 95.00    ]: STLK_USB_N, STLK_USB_P

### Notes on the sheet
- ST-LINK USB CONNECTOR
- STLINK
- TARGET MCU
- (near U22) STLINK MCU
- (near CN11) Reserved
- (near CN11) 1
- 5V_STLK OVERCURRENT PROTECTION MANAGEMENT
- T_PWR_SEL2/PD5
- T_PWR_SEL1/PD4
- (current limit: 550mA)
- (current limit: 1.66A)
- Power1.5.SNK
- Power3.0.SNK
- PowerDefault.SNK
- Hi-Z
- 0
- (current limit: 3.2A)
- Hi-Z = IO set in high impedance
- (near R133) (1): NOT FITTED FOR DEBUG WITH INTERNAL STLINK (DEFAULT)
- (near R133) (1): FITTED FOR DEBUG WITH EXTERNAL DEBUGER
- Or output STLINK IOs isolated (Hi-Z)
- LED POWER STATUS
- LED STLINK
- PA14
- PA13
- PA15
- (near CN12) JRCLK
- (near CN12) KEY
- (near CN12) JTMS
- (near CN12) JTCK
- (near CN12) JTDO
- (near CN12) JTDI
- PA9
- PB3
- PA10

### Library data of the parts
C1 C2 C5-C19 C68 C90-C93 = MCD-00006: Capacitor, MLCC, 100nF, 16V, X7R, 10%, 0402, T=0.5mm; Manufacturer_Part_Number: CC0402KRX7R7BB104; Manufacturer: YAGEO; Alternate_Manufacturer_Part_Number: GCM155R71C104KA55D; Alternate_Manufacturer: MURATA; Provided_By: SUBCO
C20 C21 C78 = MCD-02198: Capacitor, MLCC, 10nF, 50V, X7R, +/-10%, 0402, T=0.5mm; Part_Preference: Recommended; Manufacturer: YAGEO; Manufacturer_Part_Number: CC0402KRX7R9BB103; Order_Code_RS: 6169644; Component_Country_Of_Origin: China
C57 = MCD-00205: Capacitor, MLCC, 100pF, 50V, NPO, +/-5%, 0402, T=0.5mm; Part_Preference: Recommended; Manufacturer: YAGEO; Manufacturer_Part_Number: CC0402JRNPO9BN101; Component_Country_Of_Origin: China
C59 C70 C77 = MCD-02606: Capacitor, MLCC, 2.2uF, 6.3V, X5R, +/-10%, 0402, T=0.5mm; Part_Preference: Recommended; Manufacturer: YAGEO; Manufacturer_Part_Number: CC0402KRX5R5BB225; Order_Code_RS: 1992205
C60 = MCD-00099: Capacitor, MLCC, 10uF, 10V, X5R, +/-10%, 0603, T=0.8mm; Part_Preference: Recommended; Manufacturer: MURATA; Manufacturer_Part_Number: GRM188R61A106KE69D; Order_Code_RS: 170-6168; Component_Country_Of_Origin: Japan; ShowFields: YES; ID: 2770
C61 = MCD-02355: Capacitor, MLCC, 100nF, 25V, X7R, +/-10%, 0402, T=0.5mm; Part_Preference: Recommended; Manufacturer: WALSIN; Manufacturer_Part_Number: 0402B104K250CT; Order_Code_RS: 176-3114; Component_Country_Of_Origin: Unknown; ShowFields: YES; ID: 4461
C64 C66 = MCD-00099: Capacitor, MLCC, 10uF, 10V, X5R, +/-10%, 0603, T=0.8mm; Part_Preference: Recommended; Manufacturer: MURATA; Manufacturer_Part_Number: GRM188R61A106KE69D; Order_Code_RS: 170-6168; Component_Country_Of_Origin: Japan
C65 = MCD-02355: Capacitor, MLCC, 100nF, 25V, X7R, +/-10%, 0402, T=0.5mm; Part_Preference: Recommended; Manufacturer: WALSIN; Manufacturer_Part_Number: 0402B104K250CT; Order_Code_RS: 176-3114; Component_Country_Of_Origin: Unknown
C71 C72 = MCD-01774: Capacitor, MLCC, 2.7pF, 50V, NPO, +/-0.1pF, 0402, T=0.5mm; Part_Preference: Recommended; Manufacturer: YAGEO; Manufacturer_Part_Number: CC0402BRNPO9BN2R7; Component_Country_Of_Origin: China
C80 = MCD-02372: Capacitor, MLCC, 2.2uF, 25V, X7R, +/-10%, 0805, T=1,25mm; Manufacturer_Part_Number: GRM21BR71E225KE11L; Manufacturer: MURATA; Part_Preference: Recommended; ECCN_US: EAR99; ECCN_EU: NEC; Provided_By: SUBCO
CN10 = MCD-02273: USB_TypeC, 24pins, RA, TH, T=1.9mm (USB certified); Part_Type: Connector; Part_Preference: Recommended; Manufacturer: WURTH ELEKTRONIK; Manufacturer_Part_Number: 632723300011; Component_Country_Of_Origin: China; ShowFields: YES; ID: 4373
CN11 = MCD-00029: Header, 4x1, 2,54mm, VR, TH, Height 5.84mm/2.54mm; Manufacturer_Part_Number: TSW-104-07-x-S; Manufacturer: SAMTEC; Part_Type: Connector; Provided_By: SUBCO
CN12 = MCD-01226: Header, 5x2, 1.27mm, VR, SMD, T=5.97mm/3.05mm; Part_Type: Connector; Part_Preference: Recommended; Manufacturer: SAMTEC; Manufacturer_Part_Number: FTSH-105-01-L-DV-K; Order_Code_RS: 159-2332; Component_Country_Of_Origin: China, Costa Rica, Malaysia, United States, Vietnam
D2-D4 = MCD-01677: Small signal Schottky diodes; BMS_Part_Number: 9151123; Part_Type: Diode; Part_Preference: Recommended; Manufacturer: STMICROELECTRONICS; Manufacturer_HQ_COO: EU; Component_Country_Of_Origin: China; ShowFields: YES; ID: 3777
JP1 JP5 = MCD-00045: Header, 2x1, 2,54mm, VR, TH, Height 5.84mm/2.54mm; Part_Preference: Recommended; Part_Type: Connector; Manufacturer: SAMTEC; Manufacturer_Part_Number: TSW-102-07-G-S; Alternate_Manufacturer: JIUBABA; LIANYI; Alternate_Manufacturer_Part_Number: 313102S111116;313102S111116
LD8 LD9 = MCD-02631: LED Bicolor, Green/Red, 2V, 20mA,  4-PLCC; Part_Type: Display; Part_Preference: Recommended; Manufacturer: WURTH ELEKTRONIK; Manufacturer_Part_Number: 150141SV73110; Order_Code_RS: 184-6963
R1-R3 R63 R82-R84 R132 R134-R136 = MCD-00059: Resistor,100K,0402,1%,1/16W; Manufacturer_Part_Number: RC0402FR-07100KL; Manufacturer: YAGEO; Alternate_Manufacturer_Part_Number: RT0402FRE07100KL; Provided_By: Subcon; Initial_Board_Reference: MB1274
R45 R48 R64 R74 = MCD-00333: Resistor, 5K1, 0402, +/-1%, 1/16W; Part_Preference: Recommended; Manufacturer: YAGEO; Manufacturer_Part_Number: RC0402FR-075K1L
R46 R47 R133 R137-R139 = MCD-00059: Resistor, 100K, 0402, +/-1%, 1/16W; Part_Preference: Recommended; Manufacturer: YAGEO; Manufacturer_Part_Number: RC0402FR-07100KL; Component_Country_Of_Origin: China; ShowFields: YES; ID: 2533
R58 = MCD-00067: Resistor, 100R, 0402, +/- 1%, 1/16W; Part_Preference: Recommended; Manufacturer: YAGEO; Manufacturer_Part_Number: RC0402FR-07100RL; Component_Country_Of_Origin: China; ShowFields: YES; ID: 2527
R59 R130 = MCD-02665: Resistor, 1K, 0402, +/-0.1%, 1/16W, +/-25ppm/°C; Part_Preference: Recommended; Manufacturer: YAGEO; Manufacturer_Part_Number: RT0402BRD071KL; Order_Code_RS: 199-1298
R60 R131 = MCD-00062: Resistor, 330R, 0402, +/-1%, 1/16W; Part_Preference: Recommended; Manufacturer: YAGEO; Manufacturer_Part_Number: RC0402FR-07330RL; Component_Country_Of_Origin: China
R61 R69 R72 R78 = MCD-00481: Resistor,47R,0402,1%,1/16W; Manufacturer_Part_Number: RC0402FR-0747RL; Manufacturer: YAGEO; Provided_By: SUBCO; Initial_Board_Reference: MBxxxx
R65-R67 R85 = MCD-00053: Resistor,10K,0402,1%,1/16W; Manufacturer_Part_Number: RC0402FR-0710KL; Manufacturer: YAGEO; Provided_By: SUBCO
R68 R75 = MCD-00052: as R97 on sheet JTAG
R71 = MCD-00185: Resistor,3K,0402,1%,1/16W; Manufacturer_Part_Number: RC0402FR-073KL; Manufacturer: YAGEO; Provided_By: SUBCO
R86 = MCD-00409: Resistor, 1K8, 0402, +/-1%, 1/16W; Part_Preference: Recommended; Manufacturer: YAGEO; Manufacturer_Part_Number: RC0402FR-071K8L; Component_Country_Of_Origin: China
R87 = MCD-00185: Resistor, 3K, 0402, +/-1%, 1/16W; Part_Preference: Recommended; Manufacturer: YAGEO; Manufacturer_Part_Number: RC0402FR-073KL; Component_Country_Of_Origin: China
R128 = MCD-00381: Resistor, 1K3, 0402, +/-1%, 1/16W; Part_Preference: Recommended; Manufacturer: YAGEO; Manufacturer_Part_Number: RC0402FR-071K3L; Component_Country_Of_Origin: China; ShowFields: YES; ID: 2898
R129 = MCD-02455: Resistor, 3K9, 0402, +/-1%, 1/16W, +/-100ppm/°C; Part_Preference: Recommended; Manufacturer: YAGEO; Manufacturer_Part_Number: RC0402FR-073K9L; Order_Code_RS: 198-7783; Component_Country_Of_Origin: China; ShowFields: YES; ID: 4561
TP13 = MCD-00074: Test Point 1mm; Part_Type: Mechanical
U3 U4 = MCD-00136: Dual Transil array for ESD protection; BMS_Part_Number: 9151112; Part_Type: Diode; Part_Preference: Recommended; Manufacturer: STMICROELECTRONICS; Manufacturer_HQ_COO: EU; Component_Country_Of_Origin: China
U13 = MCD-01207: High power Transient voltage suppressor:25V/35A EOS and ESD transients protection.; Part_Type: Diode; Manufacturer: STMICROELECTRONICS; BMS_Part_Number: 9179045; ECCN_US: EAR99; ECCN_EU: NEC; Provided_By: SUBCO with ST control
U19 = MCD-00649: Common mode filter with ESD protection for USB 2.0 interface; BMS_Part_Number: 9151138; Part_Type: Diode; Part_Preference: Recommended; Manufacturer: STMICROELECTRONICS; Manufacturer_HQ_COO: EU; Component_Country_Of_Origin: China; ShowFields: YES; ID: 3094
U21 = MCD-00159: 500mA, Enhanced single channel power switches with active high enable pin; BMS_Part_Number: 9159009; Part_Type: IC; Part_Preference: Recommended; Manufacturer: STMICROELECTRONICS; Manufacturer_HQ_COO: EU; Component_Country_Of_Origin: Malaysia; ShowFields: YES; ID: 2708
U22 = MCD-02706: STM32F723IEK  (STM32F7) BGA176; BMS_Part_Number: 9175300; Part_Type: IC; Part_Preference: Recommended; Manufacturer: STMICROELECTRONICS; Order_Code_RS: 135-8241; ShowFields: YES; ID: 4812
U24 = MCD-02514: LDO, 3.3V, 300mA, High input voltage: 2.5V to 28V, SOT23-5L; Part_Type: IC; Part_Preference: Recommended; Manufacturer: STMICROELECTRONICS
U26 U27 = MCD-01945: 4-bit dual supply translating transceiver with configurable voltage translation; 3-state; Part_Type: IC; Manufacturer_Part_Number: 74AVC4TD245BQ,115; Manufacturer: NEXPERIA; Part_Preference: Recommended
U34 = MCD-02532: eFuse with Fast Overvoltage Protection 2.7V to 18V 4A 34mOhm 8-Pin WSON; Part_Type: IC; Part_Preference: Recommended; Manufacturer: TEXAS INSTRUMENTS; Order_Code_RS: NA
X1 = MCD-01036: Crystal, 24MHz, 6pF, +/-20ppm, 80R, 2x1.6mm; BMS_Part_Number: 9157045; Part_Type: Crystal_Osc; Part_Preference: Recommended; Manufacturer: NDK; Manufacturer_Part_Number: NX2016SA-24MHZ-EXS00A-CS10820; Component_Country_Of_Origin: Unknown

## Sheet Board_power.SchDoc: Board power
size A4; Date: Not used; ApprovedBy: Not used; CheckedBy: Not used; Author: Not used; CompanyName: STMicroelectronics; DrawnBy: Not used; Engineer: Not used; Organization: Not used; Address1: Not used; Address2: Not used; Address3: Not used; Address4: Not used; DocumentNumber: 5; Revision: Not used; SheetNumber: 5; SheetTotal: 15
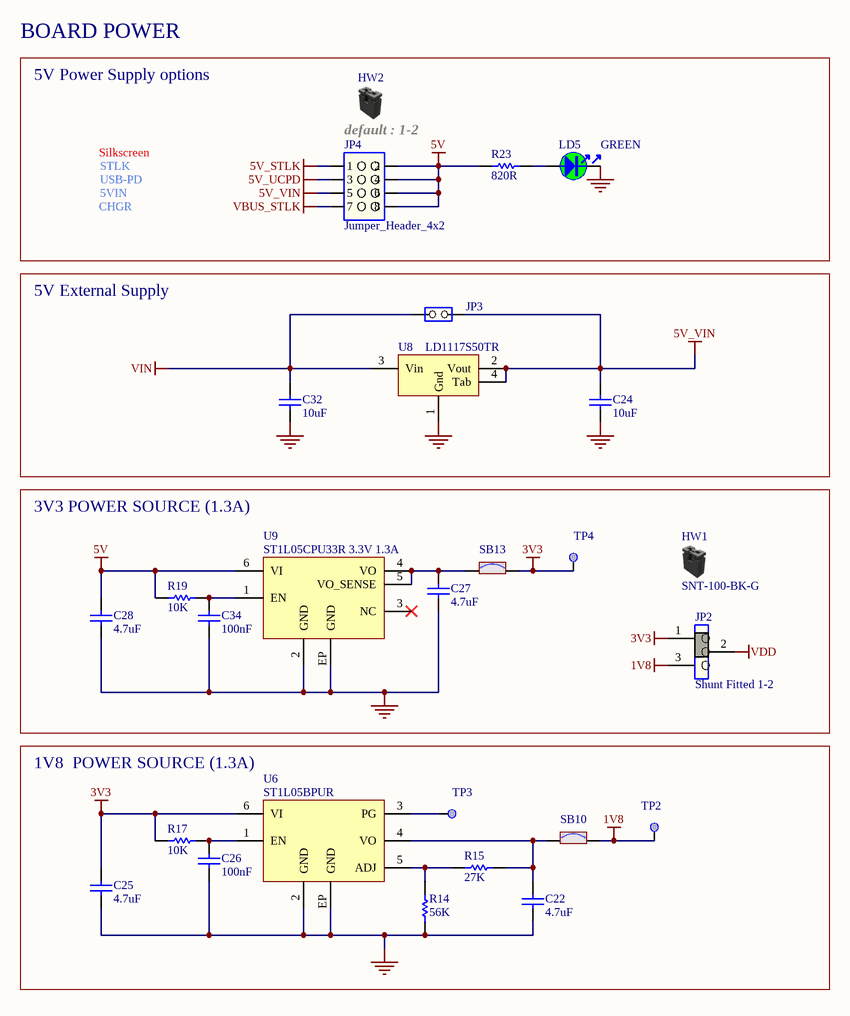
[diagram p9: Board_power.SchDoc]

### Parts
C22  value 4.7uF  [C0603]  (hidden comment: Capacitor)
C24  value 10uF  [C0805]  (hidden comment: Capacitor)
C25  value 4.7uF  [C0603]  (hidden comment: Capacitor)
C26  value 100nF  [C0402]  (hidden comment: Capacitor)
C27  value 4.7uF  [C0603]  (hidden comment: Capacitor)
C28  value 4.7uF  [C0603]  (hidden comment: Capacitor)
C32  value 10uF  [C0805]  (hidden comment: Capacitor)
C34  value 100nF  [C0402]  (hidden comment: Capacitor)
HW1  value SNT-100-BK-G  (hidden comment: Shunt Black 2.54mm)  (mechanical)
HW2  Shunt Black 2.54mm  (value not drawn)  (mechanical)
JP2  value Shunt Fitted 1-2  [CON_SAMTEC_TSW-103-07-F-S]  (hidden comment: Jumper_Header 3x1 Fitted 1-2)
JP3  Jumper_Header 2x1  [CON_SAMTEC_TSW-102-07-G-S]  (value not drawn)
JP4  value Jumper_Header_4x2  [CON_SAMTEC_TSM-104-01-X-DV]  (hidden comment: Jumper_Header 4x2)
LD5  value GREEN  [LED_0603_VISHAY_VLMTG1300-GS08_GREEN_1A2K_H0P8]  (hidden comment: LED_green)
R14  value 56K  [R0402]  (hidden comment: Resistor)
R15  value 27K  [R0402]  (hidden comment: Resistor)
R17  value 10K  [R0402]  (hidden comment: Resistor)
R19  value 10K  [R0402]  (hidden comment: Resistor)
R23  value 820R  [R0603]  (hidden comment: Resistor)
SB10  SB_ON  [SOLDER-BRIDGE_R0603-0R]  (value not drawn)
SB13  SB_ON  [SOLDER-BRIDGE_R0603-0R]  (value not drawn)
TP2  Test Point  [TP_SMD_2MM]  (value not drawn)  (no BOM)
TP3  Test Point  [TP_SMD_2MM]  (value not drawn)  (no BOM)
TP4  Test Point  [TP_SMD_2MM]  (value not drawn)  (no BOM)
U6  ST1L05BPUR  [ICC_DFN6-EPAD_3X3_P095]
U8  LD1117S50TR  [REG_SOT223-TAB]
U9  value ST1L05CPU33R 3.3V 1.3A  [ICC_DFN6-EPAD_3X3_P095]  (hidden comment: ST1L05CPU33R)

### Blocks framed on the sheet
BOARD POWER: HW2 JP4 LD5 R23
5V External Supply: C24 C32 JP3 U8
3V3 POWER SOURCE (1.3A): C27 C28 C34 HW1 JP2 R19 SB13 TP4 U9
1V8  POWER SOURCE (1.3A): C22 C25 C26 R14 R15 R17 SB10 TP2 TP3 U6

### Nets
1V8: JP2.3 SB10.2 TP2.1
3V3: C25.1 JP2.1 R17.1 SB13.2 TP4.1 U6.6(VI)
5V: C28.2 JP4.2 JP4.4 JP4.6 JP4.8 R19.1 R23.1 U9.6(VI)
5V_STLK: JP4.1
5V_UCPD: JP4.3
5V_VIN: C24.2 JP3.2(NO) JP4.5 U8.2(Vout) U8.4(Tab)
GND: C22.1 C24.1 C25.2 C26.1 C27.1 C28.1 C32.1 C34.1 LD5.2 R14.1 U6.2(GND) U6.EP(GND) U8.1(Gnd) U9.2(GND) U9.EP(GND)
VBUS_STLK: JP4.7
VDD: JP2.2
VIN: C32.2 JP3.1(COMMON) U8.3(Vin)
NetC22_2: C22.2 R15.2 SB10.1 U6.4(VO)
NetC26_2: C26.2 R17.2 U6.1(EN)
NetC27_2: C27.2 SB13.1 U9.4(VO) U9.5(VO_SENSE)
NetC34_2: C34.2 R19.2 U9.1(EN)
NetLD5_1: LD5.1 R23.2
NetR14_2: R14.2 R15.1 U6.5(ADJ)
NetTP3_1: TP3.1 U6.3(PG)

Not connected (* = marked no-connect by the designer): U9 3(NC)*

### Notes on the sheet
- 5V Power Supply options
- Silkscreen
- default : 1-2
- CHGR
- STLK
- USB-PD
- 5VIN

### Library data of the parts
C22 C25 C27 C28 = MCD-00009: Capacitor, MLCC, 4.7uF, 16V, X5R, 10%, 0603, T=0.8mm; Manufacturer_Part_Number: CC0603KRX5R7BB475; Manufacturer: YAGEO; Provided_By: SUBCO
C24 C32 = MCD-00014: Capacitor, MLCC, 10uF, 25V, X5R, 10%, 0805, T=0,85mm; Manufacturer_Part_Number: CC0805KRX5R8BB106; Manufacturer: YAGEO; Provided_By: SUBCO
C26 C34 = MCD-00006: as C1 on sheet STLINK_V3EC
HW1 = MCD-00043: SHUNT 2.54mm BLACK; Part_Type: Misc; Part_Preference: Recommended; Manufacturer: SAMTEC; Alternate_Manufacturer: JIUBABA; Alternate_Manufacturer_Part_Number: 316102S111A
HW2 = MCD-00043: SHUNT 2.54mm BLACK; Part_Type: Mechanical; Manufacturer: SAMTEC; Alternate_Manufacturer_Part_Number: 316102S111A; Alternate_Manufacturer: JIUBABA; Value: SNT-100-BK-G; Provided_By: SUBCO
JP2 = MCD-00684: Header, 3x1, 2,54mm, VR, TH, Height 5.84mm/2.54mm - Shunt Fitted 1-2 by default; Part_Type: Connector; Part_Preference: Recommended; Manufacturer: SAMTEC; Manufacturer_Part_Number: TSW-103-07-F-S
JP3 = MCD-00045: Header, 2x1, 2,54mm, VR, TH, Height 5.84mm/2.54mm; Part_Type: Connector; Manufacturer_Part_Number: TSW-102-07-x-S; Manufacturer: SAMTEC; Value: Shunt not fitted; Provided_By: Subcon; Initial_Board_Reference: MB1274; Remark: 3D KO: BZ: 40098
JP4 = MCD-00044: Header, 4x2, 2,54mm, VR, SMT, Height 5.84mm/2.54mm; Part_Type: Connector; Part_Preference: Recommended; Manufacturer: SAMTEC; Manufacturer_Part_Number: TSM-104-01-G-DV
LD5 = MCD-00589: LED Green, 0603 SMD, Fw Voltage = 2.8V - 3.6V; Part_Type: Display; Manufacturer_Part_Number: VLMTG1300-GS08; Manufacturer: VISHAY; Alternate_Manufacturer_Part_Number: LG Q396-PS-35; Alternate_Manufacturer: OSRAM OPTO SEMICONDUCTORS; Order_Code_RS: 7730452; Provided_By: SUBCO
R14 = MCD-00493: Resistor,56K,0402,1%,1/16W; Part_Preference: Recommended; Manufacturer: YAGEO; Manufacturer_Part_Number: RC0402FR-0756KL
R15 = MCD-00443: Resistor,27K,0402,1%,1/16W; Part_Preference: Recommended; Manufacturer: YAGEO; Manufacturer_Part_Number: RC0402FR-0727KL
R17 R19 = MCD-00053: as R65-R67 on sheet STLINK_V3EC
R23 = MCD-00528: Resistor,820R,0603,1%,1/10W; Manufacturer_Part_Number: RC0603FR-07820RL; Manufacturer: YAGEO; BMS_Part_Number: 9129759; Provided_By: SUBCO
SB10 SB13 = MCD-00071: as SB17 on sheet JTAG
TP2-TP4 = MCD-00177: Test Point 2mm; Part_Type: Mechanical
U6 = MCD-00581: LDO Linear Voltage Regulator IC Positive Adjustable 1 Output Adjustable 1.3A 6-DFN (3x3); BMS_Part_Number: 9176239; Part_Preference: Recommended; Manufacturer: STMICROELECTRONICS; Manufacturer_HQ_COO: EU
U8 = MCD-00088: IC REG LDO 5V 0.8A SOT223; Manufacturer: STMICROELECTRONICS; BMS_Part_Number: 9176133; Provided_By: SUBCO with ST control
U9 = MCD-01025: LDO, 3.3V, 1.3A, Very low quiescent current BiCMOS voltage regulator; Part_Type: IC; Manufacturer: STMICROELECTRONICS; BMS_Part_Number: 9176246; Provided_By: SUBCO with ST control

## Sheet STM32_microcontroller_power.SchDoc: STM32 microcontroller power
size A4; Date: Not used; ApprovedBy: Not used; CheckedBy: Not used; Author: Not used; CompanyName: STMicroelectronics; DrawnBy: Not used; Engineer: Not used; Organization: Not used; Address1: Not used; Address2: Not used; Address3: Not used; Address4: Not used; DocumentNumber: 4; Revision: Not used; SheetNumber: 4; SheetTotal: 15
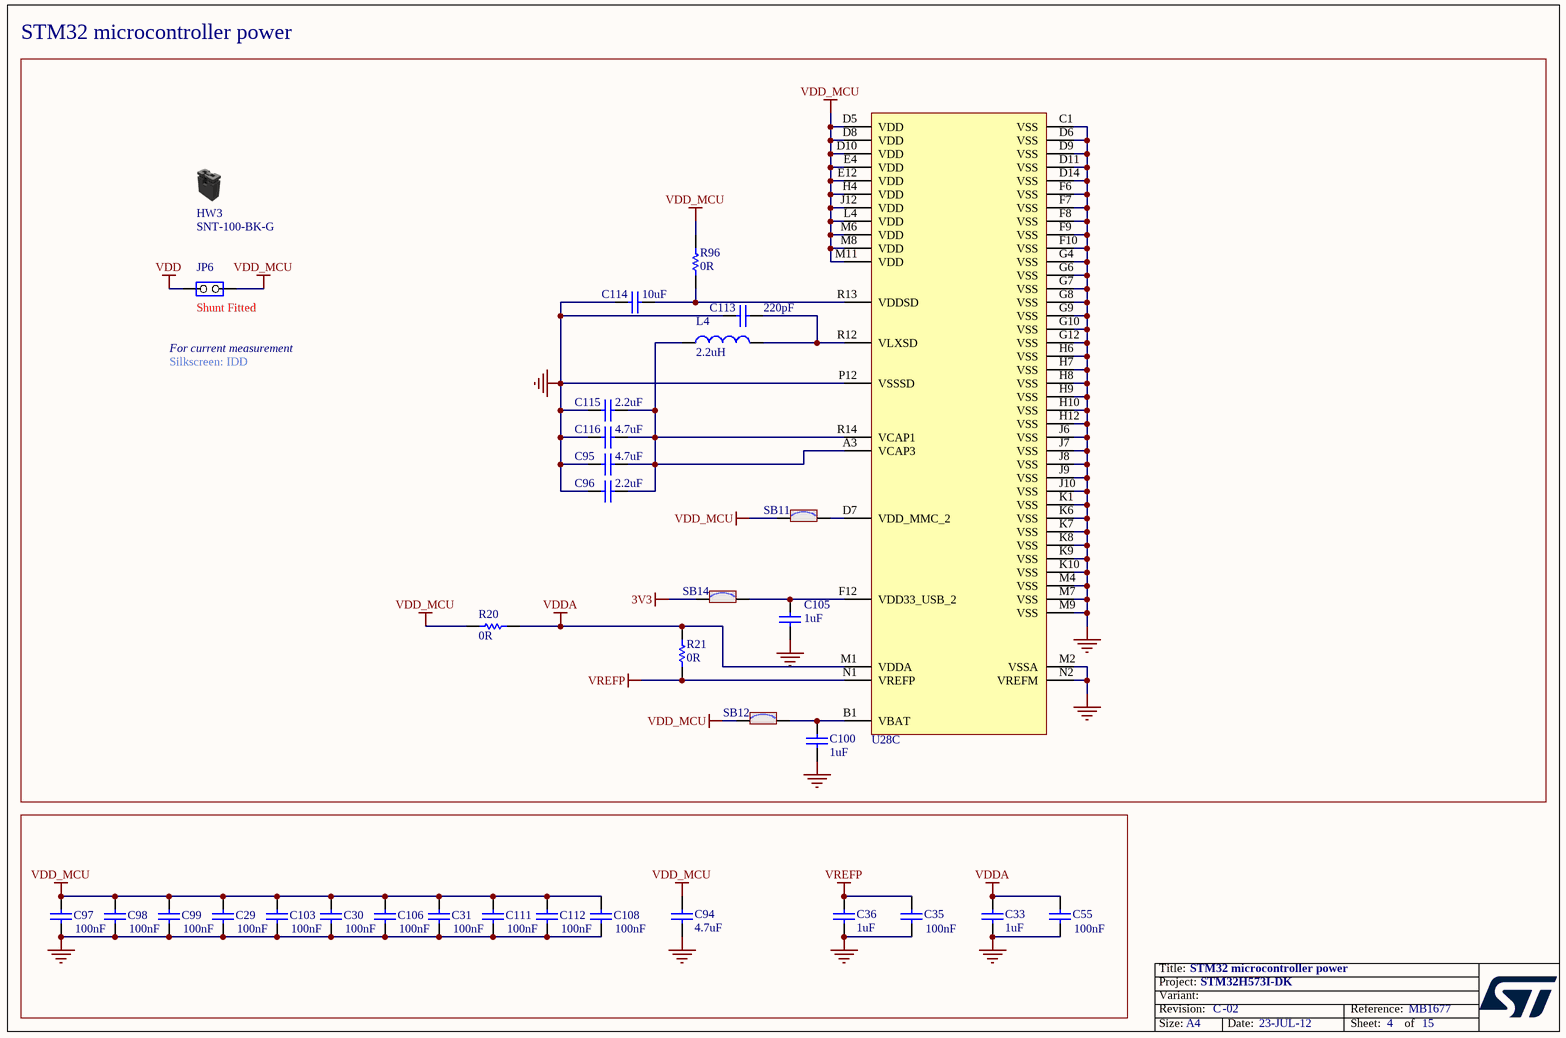
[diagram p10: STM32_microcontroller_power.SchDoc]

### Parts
C29  value 100nF  [C0402]  (hidden comment: Capacitor)
C30  value 100nF  [C0402]  (hidden comment: Capacitor)
C31  value 100nF  [C0402]  (hidden comment: Capacitor)
C33  value 1uF  [C0402]  (hidden comment: Capacitor)
C35  value 100nF  [C0402]  (hidden comment: Capacitor)
C36  value 1uF  [C0402]  (hidden comment: Capacitor)
C55  value 100nF  [C0402]  (hidden comment: Capacitor)
C94  value 4.7uF  [C0603]  (hidden comment: Capacitor)
C95  value 4.7uF  [C0402]  (hidden comment: Capacitor)
C96  value 2.2uF  [C0402]  (hidden comment: Capacitor)
C97  value 100nF  [C0402]  (hidden comment: Capacitor)
C98  value 100nF  [C0402]  (hidden comment: Capacitor)
C99  value 100nF  [C0402]  (hidden comment: Capacitor)
C100  value 1uF  [C0402]  (hidden comment: Capacitor)
C103  value 100nF  [C0402]  (hidden comment: Capacitor)
C105  value 1uF  [C0603]  (hidden comment: Capacitor)
C106  value 100nF  [C0402]  (hidden comment: Capacitor)
C108  value 100nF  [C0402]  (hidden comment: Capacitor)
C111  value 100nF  [C0402]  (hidden comment: Capacitor)
C112  value 100nF  [C0402]  (hidden comment: Capacitor)
C113  value 220pF  [C0402]  (hidden comment: Capacitor)
C114  value 10uF  [C0402]  (hidden comment: Capacitor)
C115  value 2.2uF  [C0402]  (hidden comment: Capacitor)
C116  value 4.7uF  [C0402]  (hidden comment: Capacitor)
HW3  value SNT-100-BK-G  (hidden comment: Shunt Black 2.54mm)  (mechanical)
JP6  Jumper_Header 2x1  [CON_SAMTEC_TSW-102-07-G-S]  (value not drawn)
L4  value 2.2uH  [L0805_H0P9]  (hidden comment: Inductor)
R20  value 0R  [R0603]  (hidden comment: Resistor)
R21  value 0R  [R0603]  (hidden comment: Resistor)
R96  value 0R  [R0603]  (hidden comment: Resistor)
SB11  SB_ON  [SOLDER-BRIDGE_R0603-0R]  (value not drawn)
SB12  SB_ON  [SOLDER-BRIDGE_R0603-0R]  (value not drawn)
SB14  SB_ON  [SOLDER-BRIDGE_R0603-0R]  (value not drawn)
U28  STM32H573IIK3Q  [ICC_UFBGA201_176+25_10X10_P065]  (value not drawn)  (part C of 3)

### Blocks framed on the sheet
STM32 microcontroller power: C95 C96 C100 C105 C113-C116 HW3 JP6 L4 R20 R21 R96 SB11 SB12 SB14 U28

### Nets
3V3: SB14.1
GND: C29.2 C30.2 C31.2 C33.1 C35.1 C36.1 C55.1 C94.1 C95.2 C96.1 C97.2 C98.2 C99.2 C100.1 C103.2 C105.1 C106.2 C108.2 C111.2 C112.2 C113.1 C114.1 C115.1 C116.2 U28.C1(VSS) U28.D6(VSS) U28.D9(VSS) U28.D11(VSS) U28.D14(VSS) U28.F6(VSS) U28.F7(VSS) U28.F8(VSS) U28.F9(VSS) U28.F10(VSS) U28.G4(VSS) U28.G6(VSS) U28.G7(VSS) U28.G8(VSS) U28.G9(VSS) U28.G10(VSS) U28.G12(VSS) U28.H6(VSS) U28.H7(VSS) U28.H8(VSS) U28.H9(VSS) U28.H10(VSS) U28.H12(VSS) U28.J6(VSS) U28.J7(VSS) U28.J8(VSS) U28.J9(VSS) U28.J10(VSS) U28.K1(VSS) U28.K6(VSS) U28.K7(VSS) U28.K8(VSS) U28.K9(VSS) U28.K10(VSS) U28.M2(VSSA) U28.M4(VSS) U28.M7(VSS) U28.M9(VSS) U28.N2(VREFM) U28.P12(VSSSD)
VDD: JP6.1(COMMON)
VDD_MCU: C29.1 C30.1 C31.1 C94.2 C97.1 C98.1 C99.1 C103.1 C106.1 C108.1 C111.1 C112.1 JP6.2(NO) R20.1 R96.2 SB11.1 SB12.1 U28.D5(VDD) U28.D8(VDD) U28.D10(VDD) U28.E4(VDD) U28.E12(VDD) U28.H4(VDD) U28.J12(VDD) U28.L4(VDD) U28.M6(VDD) U28.M8(VDD) U28.M11(VDD)
VDDA: C33.2 C55.2 R20.2 R21.1 U28.M1(VDDA)
VREFP: C35.2 C36.2 R21.2 U28.N1(VREFP)
NetC95_1: C95.1 C96.2 C115.2 C116.1 L4.1 U28.A3(VCAP3) U28.R14(VCAP1)
NetC100_2: C100.2 SB12.2 U28.B1(VBAT)
NetC105_2: C105.2 SB14.2 U28.F12(VDD33_USB_2)
NetC113_2: C113.2 L4.2 U28.R12(VLXSD)
NetC114_2: C114.2 R96.1 U28.R13(VDDSD)
NetSB11_2: SB11.2 U28.D7(VDD_MMC_2)

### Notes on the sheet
- (near JP6) Shunt Fitted
- For current measurement
- Silkscreen: IDD

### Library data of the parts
C29-C31 C35 C55 C97-C99 C103 C106 C108 C111 C112 = MCD-00006: as C1 on sheet STLINK_V3EC
C33 C36 C100 = MCD-01722: Capacitor, 1uF, 10V, X5R, 10%, 0402, T=0.5mm; Manufacturer_Part_Number: CC0402KRX5R6BB105; Manufacturer: YAGEO; Provided_By: SUBCO
C94 = MCD-00009: as C22 on sheet Board_power
C95 C116 = MCD-01356: Capacitor, MLCC, 4.7uF, 6V3, X5R, +/-20%, 0402, T=0,5mm; Part_Preference: Recommended; Manufacturer: MURATA; Manufacturer_Part_Number: GRM155R60J475ME47; Alternate_Manufacturer_Part_Number: GRM155R60J475ME87; Order_Code_RS: 814-5230
C96 C115 = MCD-01823: Capacitor,MLCC, 2.2uF, 6V3, X5R,+/-10%, 0402, T=0.5mm; Part_Preference: Recommended; Manufacturer: MURATA; Manufacturer_Part_Number: GRM155R60J225KE95D; Order_Code_RS: 172-6478
C105 = MCD-00010: Capacitor, MLCC, 1uF, 16V, X5R, 10%, 0603, T=0,8mm; Manufacturer_Part_Number: CC0603KRX5R7BB105; Manufacturer: YAGEO; Provided_By: SUBCO
C113 = MCD-01225: Capacitor, MLCC, 220pF, 50V, NPO, +/-5%, 0402, T=0,5mm; Part_Preference: Recommended; Manufacturer: YAGEO; Manufacturer_Part_Number: CC0402JRNPO9BN221; Order_Code_RS: 616-9284
C114 = MCD-01355: Capacitor, MLCC, 10uF, 4V, X5R, +/-20%, 0402, T=0,5mm; Part_Preference: Recommended; Manufacturer: MURATA; Manufacturer_Part_Number: GRM155R60G106ME44; Order_Code_RS: 172-6477
HW3 = MCD-00043: SHUNT 2.54mm BLACK; Manufacturer: SAMTEC; Part_Type: Mechanical; Alternate_Manufacturer_Part_Number: 316102S111A; Alternate_Manufacturer: JIUBABA; Provided_By: SUBCO
JP6 = MCD-00045: Header, 2x1, 2,54mm, VR, TH, Height 5.84mm/2.54mm; Manufacturer_Part_Number: TSW-102-07-x-S; Manufacturer: SAMTEC; Part_Type: Connector; Alternate_Manufacturer_Part_Number: 313102S111116; Alternate_Manufacturer: JIUBABA; Value: Shunt not fitted; Provided_By: SUBCO
L4 = MCD-03791: Inductor 2.2uH, +/-20%, 1.8A, 0.138Ω, 0805; Part_Preference: Recommended; Manufacturer: MURATA; Manufacturer_Part_Number: DFE21CCN2R2MELL; Order_Code_RS: NA; Component_Country_Of_Origin: Vietnam°; ShowFields: YES; ID: 5907
R20 R21 = MCD-00056: Resistor,0R,0603,5%,1/10W; Manufacturer_Part_Number: RC0603JR-070RL; Manufacturer: YAGEO; Provided_By: SUBCO
R96 = MCD-00056: Resistor,0R,0603,5%,1/10W; Part_Preference: Recommended; Manufacturer: YAGEO; Manufacturer_Part_Number: RC0603JR-070RL
SB11 SB12 SB14 = MCD-00071: as SB17 on sheet JTAG
U28 = MCD-02379: MCU, Arm Cortex-M33, 250MHz, 32-bit MCU, 2MB Flash, 640KB SRAM, Crypto; Part_Type: IC; Manufacturer: STMICROELECTRONICS; Part_Preference: Recommended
